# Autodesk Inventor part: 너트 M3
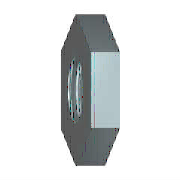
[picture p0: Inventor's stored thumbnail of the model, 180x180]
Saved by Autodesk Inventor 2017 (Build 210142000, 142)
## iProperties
Created: 2012-02
Part Number: 너트 M3
Material: 강철, 연강
Description: 6각 너트 및 6각 가는 너트 - 모따기 안된
Document SubType Name: Modeling
Standard: KS B 1012
Designer: mduedu
Standards Organization: KS
Language: ko-KR
Size Designation: B  M 3
Categories: <MemberInstance><Categories><Category DisplayName="조임쇠" InternalName="e4da775c-781d-43d5-af7c-5136215cf5a6" Mnemonic="FSTN"><Category DisplayName="너트" InternalN
Density: 7.86 g/cm^3
Mass: 0.300693 g
Surface Area: 0.894003 cm^2
Volume: 0.0382562 cm^3
Appearance: 강철
IsCustomPart: 0
Author: mduedu
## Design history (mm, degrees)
sketch "스케치1"
  geometry: L1 (1.588, -2.75)-(-1.588, -2.75); L2 (-1.588, -2.75)-(-3.175, 0); L3 (-3.175, 0)-(-1.588, 2.75); L4 (-1.588, 2.75)-(1.588, 2.75); L5 (1.588, 2.75)-(3.175, 0); L6 (3.175, 0)-(1.588, -2.75); 2 further points
  constraints: 12 end point, 1 coincident, 1 horizontal, 11 other
  dimensions: "d0" = 6.35085 distance of L5.end L2.end (= 1.1547 x SW)
extrude "본체" new body sketch "스케치1" distance "d1" = 1.8 (= KOH); taper "d2" = 0 deg
sketch "스케치2"
  geometry: 1 further point
hole "스레드" sketch "스케치2" diameter "d3" = 2.459; stored, may be unused: countersink angle "d7" = 82 deg, drill point angle "d9" = 118 deg; dims "d4" = 6, "d5" = 4, "d6" = 2, "d8" = 8
workaxis "Work Axis1"
workplane "Work Plane1"
body "Solid1"
chamfer "모따기2" distance "d12" = 0.27063 (= -0.5 x GD1 + 0.5 x NND); stored, may be unused: angle "d13" = 30 deg, second distance "d19" = 0.27063 (= -0.5 x GD1 + 0.5 x NND)
chamfer "모따기1" distance "d10" = 0.27063 (= -0.5 x GD1 + 0.5 x NND); stored, may be unused: angle "d11" = 30 deg, second distance "d18" = 0.27063 (= -0.5 x GD1 + 0.5 x NND)
other parameters: "NND" = 3 [user parameter; used in 4 equation terms], "KOH" = 1.8 [user parameter; used in 1 equation term], "SW" = 5.5 [user parameter; used in 2 equation terms], "GD1" = 2.45873 (computed from THREADDIA, PTC, TOA) [user parameter; used in 4 equation terms], "d15" = 0, "d17" = 0, "d20" = 0, "d21" = 0, "GUL" = 0.27063 (= 0.541266 x PTC) [user parameter], "THREADDIA" = 3 [user parameter; used in 1 equation term], "TOA" = 30 deg [user parameter; used in 1 equation term], "PTC" = 0.5 [user parameter; used in 4 equation terms], "E0" = 6.3525 (= 1.155 x SW) [user parameter], "GAL" = 0.27063 (= 0.541266 x PTC) [user parameter]
